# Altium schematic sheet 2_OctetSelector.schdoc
size 309 x 223 mm; Symbol: Sheet-Symbol_A4; Device: Sheet-Symbol_A4; @Project Name: ODrive Rev Motor Module; @Page Count: 5; @Update Date: 2024-10-18; @Create Date: 2024-10-18; @Schematic Name: Schematic-A; @Page No: 2; @Page Name: OctetSelector; Company: EasyEDA.com; Reviewed: EasyEDA; Version: V0.1; Page Size: A4; Part Number: JLCPCB-002; Drawn: EasyEDA; @Board Name: BaseModule; @Create Time: 22:23:50; @Update Time: 18:23:52
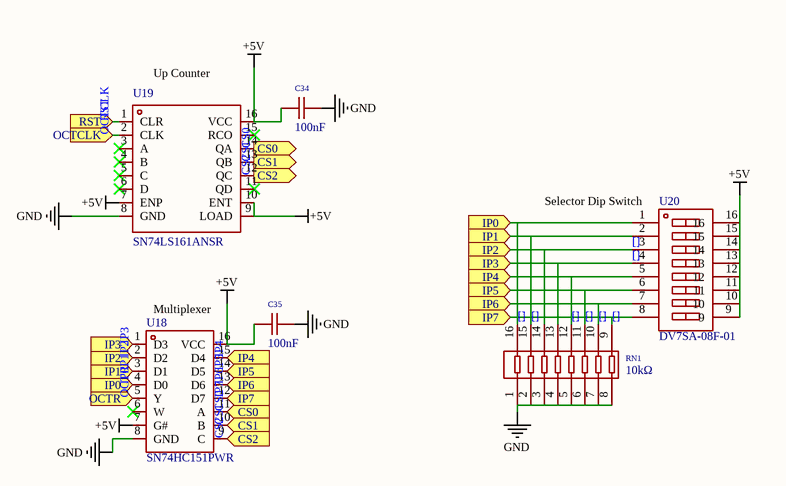
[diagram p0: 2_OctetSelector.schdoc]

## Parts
C34  100nF  [C0805]  (value not drawn)
C35  100nF  [C0805]  (value not drawn)
RN1  10kΩ  [RES-ARRAY-SMD_16P-L3.8-W1.6-P0.50-BL]  (value not drawn)
U18  SN74HC151PWR  [TSSOP-16_L5.0-W4.4-P0.65-LS6.4-BL]  (value not drawn)
U19  SN74LS161ANSR  [SOIC-16_L10.8-W5.5-P1.27-LS7.8-BL]  (value not drawn)
U20  DV7SA-08F-01  [SW-SMD_DV7SA-08F-01]  (value not drawn)

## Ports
CS0 (in), CS0 (out), CS1 (in), CS1 (out), CS2 (in), CS2 (out), IP0 (in), IP1 (in), IP2 (in), IP3 (in), IP4 (in), IP5 (in), IP6 (in), IP7 (in), OCTCLK (in), OCTR (in), RST (in)

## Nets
+5V: C34.2 C35.2 U18.7(G#) U18.16(VCC) U19.7(ENP) U19.9(LOAD) U19.10(ENT) U19.16(VCC) U20.9 U20.10 U20.11 U20.12 U20.13 U20.14 U20.15 U20.16
GND: C34.1 C35.1 RN1.1 RN1.2 RN1.3 RN1.4 RN1.5 RN1.6 RN1.7 RN1.8 U18.8(GND) U19.8(GND)
[]: RN1.9 RN1.10 RN1.11 RN1.12 RN1.13 RN1.14 RN1.15 RN1.16 U18.1(D3) U18.2(D2) U18.3(D1) U18.4(D0) U18.12(D7) U18.13(D6) U18.14(D5) U18.15(D4) U20.1 U20.2 U20.3 U20.4 U20.5 U20.6 U20.7 U20.8 ; port IP0, port IP1, port IP2, port IP3, port IP4, port IP5, port IP6, port IP7  [also labelled IP0, IP1, IP2, IP3, IP4, IP5, IP6, IP7]
CS0: U18.11(A) U19.14(QA) ; port CS0
CS1: U18.10(B) U19.13(QB) ; port CS1
CS2: U18.9(C) U19.12(QC) ; port CS2
OCTCLK: U19.2(CLK) ; port OCTCLK
OCTR: U18.5(Y) ; port OCTR
RST: U19.1(CLR) ; port RST

Not connected (* = marked no-connect by the designer): U18 6(W)*; U19 3(A)* 4(B)* 5(C)* 6(D)* 11(QD)* 15(RCO)*

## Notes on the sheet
- (near U19) Up Counter
- (near U20) Selector Dip Switch
- (near U18) Multiplexer

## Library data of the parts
C34 C35 = 0805B104K500NT: Capacitance:100nF Tolerance:±10% Tolerance:±10% Voltage Rated: Temperature Coefficient:; Manufacturer: FH(风华); Add into BOM: yes; Tolerance: ±10%
RN1 = EXB2HV103JV: Number of Resistors: Resistance:10kΩ Tolerance:±5% Tolerance:±5% Power(Watts): Temperature Coefficient:±200ppm/℃ Temperature Coefficient:±200ppm/℃ Number of Pins:; Manufacturer: PANASONIC(松下); Add into BOM: yes; Tolerance: ±5%
U18 = SN74HC151PWR: Type:Multiplexers Voltage Supply Source:Single supply Supply Voltage:2V~6V Supply Voltage:2V~6V Sink Current:7.8mA Source Current:7.8mA Operating temperature:-40℃~+85℃ Operating temperature:-40℃~+85℃; Manufacturer: TI(德州仪器); Add into BOM: yes; Supply Voltage: 2V~6V; Sink Current: 7.8mA
U19 = SN74LS161ANSR: Logic Type:Binary Counter Direction:向上计数器 Supply Voltage:4.75V Supply Voltage:4.75V Number of Elements:1 Number of Bits per Element:4 Trigger Type:Positive Edge Reset Style:异步 Timing mode:Synchronous Count Rate:25MHz Operating Temperature:0℃~+70℃ Operatin; Manufacturer: TI(德州仪器); Add into BOM: yes; Direction: 向上计数器; Supply Voltage: 4.75V; Number of Elements: 1; Number of Bits per Element: 4; Reset Style: 异步; Count Rate: 25MHz
U20 = DV7SA-08F-01: Type:Flat toggle, slotted Circuit:SPST Number of Positions:8-bit Pin Style:- Lead Pitch:- Current Rating:- Voltage Rating:- Operating Temperature:- Operating Temperature:- Operating Life:- Color:Black; Manufacturer: G-Switch(品赞); Add into BOM: yes; Circuit: SPST; Number of Positions: 8-bit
